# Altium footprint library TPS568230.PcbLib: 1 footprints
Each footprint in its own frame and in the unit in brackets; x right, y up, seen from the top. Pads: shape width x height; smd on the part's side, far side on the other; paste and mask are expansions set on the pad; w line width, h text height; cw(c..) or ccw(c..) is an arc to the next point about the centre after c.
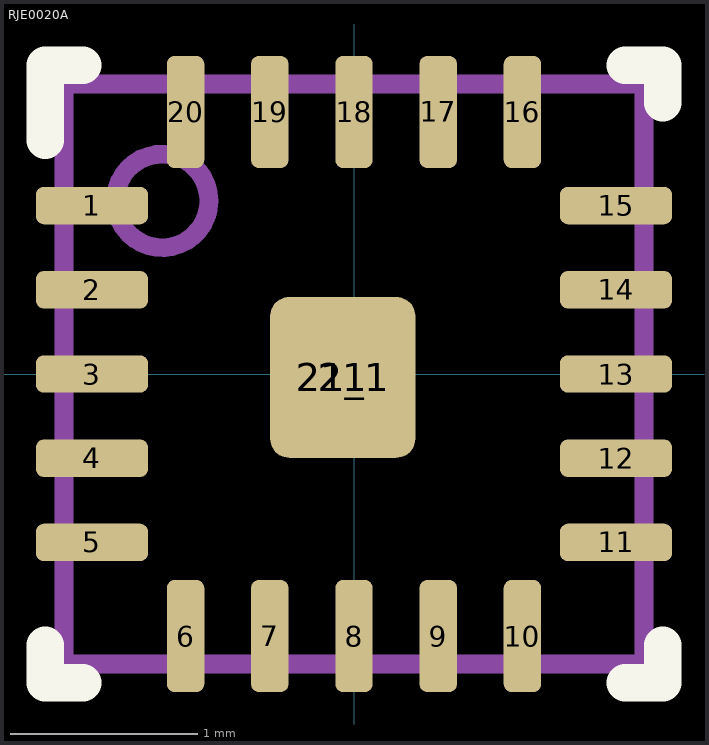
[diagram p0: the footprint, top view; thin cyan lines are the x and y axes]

## RJE0020A [mm] "QFN, 20-Leads, Body 3x3mm, Pitch 0.45mm, Thermal Pad 0.76x0.68mm"
height 1
pads (22):
  rrect42% 0.6x0.2 smd: 1(-1.4,0.9) 2(-1.4,0.45) 3(-1.4,0) 4(-1.4,-0.45) 5(-1.4,-0.9) 11(1.4,-0.9) 12(1.4,-0.45) 13(1.4,0) 14(1.4,0.45) 15(1.4,0.9)
  rrect42% 0.2x0.6 smd: 6(-0.9,-1.4) 7(-0.45,-1.4) 8(0,-1.4) 9(0.45,-1.4) 10(0.9,-1.4) 16(0.9,1.4) 17(0.45,1.4) 18(0,1.4) 19(-0.45,1.4) 20(-0.9,1.4)
  rrect26% 0.775x0.86 smd paste-0.4 mask-0.05: 21(-0.06,-0.018)
  rrect50% 0.64x0.72 on Top Paste: 21_1(-0.06,-0.018)
Top Overlay:
  lines w0.2: -1.65,-1.45 -1.65,-1.65 -1.45,-1.65 ; -1.65,1.25 -1.65,1.65 -1.45,1.65 ; 1.45,-1.65 1.65,-1.65 1.65,-1.45 ; 1.45,1.65 1.65,1.65 1.65,1.45
Mechanical 5:
  circle w0.1: c-1.025,0.925 r0.25
  lines w0.1: -1.55,-1.55 -1.55,1.55 1.55,1.55 1.55,-1.55 -1.55,-1.55
  text ".Designator" at -1.425,-0.475 h1.4
3D body: height 1, standoff 0, extent -1.549,-1.549 1.549,1.549
3D body: height 1, standoff 1, extent -1.074,0.576 -0.576,1.074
